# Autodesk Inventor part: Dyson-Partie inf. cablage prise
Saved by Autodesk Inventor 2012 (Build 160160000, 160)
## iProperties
Created: 2012-11
Part Number: Dyson-Partie inf. cablage prise
Material: Default
Document SubType Name: Modeling
Designer: Administrateur
Density: 1 g/cm^3
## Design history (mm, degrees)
node "Dyson-Partie inf. cablage prise1"
node "Dyson-Partie inf. cablage prise"
node "Base1"
